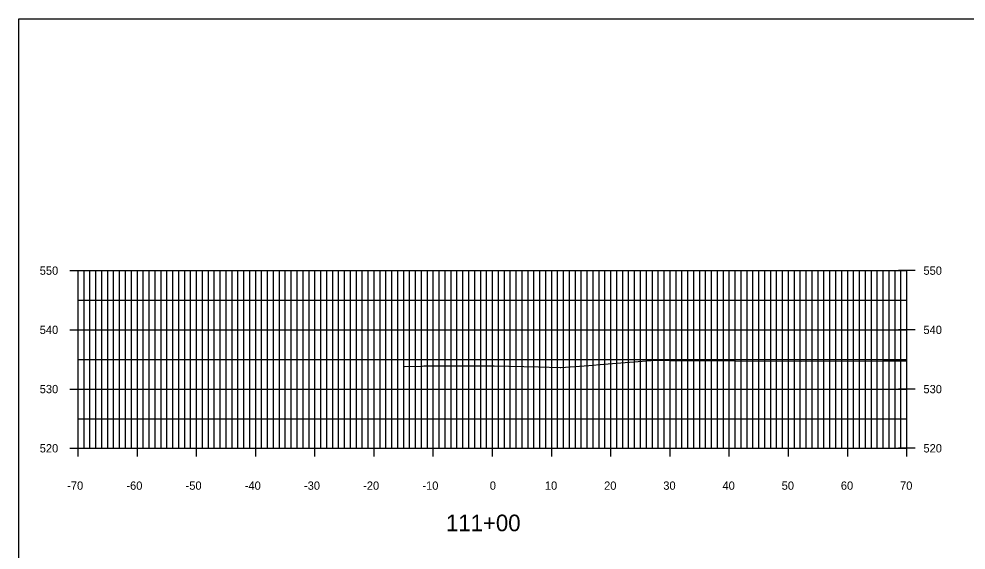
# Model space of a CAD drawing. Extents: x 1509063 to 1512863, y 401160 to 402918.
# Drawn here: x 1512542.7 to 1512702.7, y 402372.4 to 402462.1 of the extents above; entities that cross this region are included whole.
import ezdxf

# ---------------------------------------------------------------- set-up
doc = ezdxf.new("R2010")
doc.units = 0
for name, color, linetype in [('NBL1', 7, 'Continuous'), ('XAX_P', 7, 'Continuous'), ('XAXTIC_P', 7, 'Continuous'), ('XAXTXT_P_T', 7, 'Continuous'), ('XGL_P', 7, 'Continuous'), ('XSLOG', 7, 'Continuous')]:
    doc.layers.add(name, color=color, linetype=linetype)

msp = doc.modelspace()

# ---------------------------------------------------------------- linework, layer by layer
at = {"layer": 'NBL1'}
msp.add_lwpolyline([(1512862.73, 402252.08), (1512542.73, 402252.08), (1512542.73, 402462.08), (1512862.73, 402462.08)], close=True, dxfattribs=at)
at = {"layer": 'XAX_P'}
for p, q in [((1512552.73, 402389.58), (1512552.73, 402419.58)), ((1512622.73, 402389.58), (1512622.73, 402419.58)), ((1512692.73, 402389.58), (1512692.73, 402419.58)), ((1512552.73, 402389.58), (1512692.73, 402389.58))]:
    msp.add_line(p, q, dxfattribs=at)
at = {"layer": 'XAXTIC_P'}
for p, q in [((1512551.33, 402419.58), (1512554.13, 402419.58)), ((1512621.33, 402419.58), (1512624.13, 402419.58)), ((1512694.13, 402419.58), (1512691.33, 402419.58)), ((1512551.33, 402409.58), (1512554.13, 402409.58)), ((1512621.33, 402409.58), (1512624.13, 402409.58)), ((1512694.13, 402409.58), (1512691.33, 402409.58)), ((1512551.33, 402399.58), (1512554.13, 402399.58)), ((1512621.33, 402399.58), (1512624.13, 402399.58)), ((1512694.13, 402399.58), (1512691.33, 402399.58)), ((1512552.73, 402388.18), (1512552.73, 402390.98)), ((1512562.73, 402388.18), (1512562.73, 402390.98)), ((1512572.73, 402388.18), (1512572.73, 402390.98)), ((1512582.73, 402388.18), (1512582.73, 402390.98)), ((1512592.73, 402388.18), (1512592.73, 402390.98)), ((1512602.73, 402388.18), (1512602.73, 402390.98)), ((1512612.73, 402388.18), (1512612.73, 402390.98)), ((1512622.73, 402388.18), (1512622.73, 402390.98)), ((1512632.73, 402388.18), (1512632.73, 402390.98)), ((1512642.73, 402388.18), (1512642.73, 402390.98)), ((1512652.73, 402388.18), (1512652.73, 402390.98)), ((1512662.73, 402388.18), (1512662.73, 402390.98)), ((1512672.73, 402388.18), (1512672.73, 402390.98)), ((1512682.73, 402388.18), (1512682.73, 402390.98)), ((1512692.73, 402388.18), (1512692.73, 402390.98)), ((1512551.33, 402389.58), (1512554.13, 402389.58)), ((1512621.33, 402389.58), (1512624.13, 402389.58)), ((1512694.13, 402389.58), (1512691.33, 402389.58))]:
    msp.add_line(p, q, dxfattribs=at)
at = {"layer": 'XGL_P'}
for p, q in [((1512552.73, 402419.58), (1512692.73, 402419.58)), ((1512552.73, 402389.58), (1512552.73, 402419.58)), ((1512553.73, 402389.58), (1512553.73, 402419.58)), ((1512554.73, 402389.58), (1512554.73, 402419.58)), ((1512555.73, 402389.58), (1512555.73, 402419.58)), ((1512556.73, 402389.58), (1512556.73, 402419.58)), ((1512557.73, 402389.58), (1512557.73, 402419.58)), ((1512558.73, 402389.58), (1512558.73, 402419.58)), ((1512559.73, 402389.58), (1512559.73, 402419.58)), ((1512560.73, 402389.58), (1512560.73, 402419.58)), ((1512561.73, 402389.58), (1512561.73, 402419.58)), ((1512562.73, 402389.58), (1512562.73, 402419.58)), ((1512563.73, 402389.58), (1512563.73, 402419.58)), ((1512564.73, 402389.58), (1512564.73, 402419.58)), ((1512565.73, 402389.58), (1512565.73, 402419.58)), ((1512566.73, 402389.58), (1512566.73, 402419.58)), ((1512567.73, 402389.58), (1512567.73, 402419.58)), ((1512568.73, 402389.58), (1512568.73, 402419.58)), ((1512569.73, 402389.58), (1512569.73, 402419.58)), ((1512570.73, 402389.58), (1512570.73, 402419.58)), ((1512571.73, 402389.58), (1512571.73, 402419.58)), ((1512572.73, 402389.58), (1512572.73, 402419.58)), ((1512573.73, 402389.58), (1512573.73, 402419.58)), ((1512574.73, 402389.58), (1512574.73, 402419.58)), ((1512575.73, 402389.58), (1512575.73, 402419.58)), ((1512576.73, 402389.58), (1512576.73, 402419.58)), ((1512577.73, 402389.58), (1512577.73, 402419.58)), ((1512578.73, 402389.58), (1512578.73, 402419.58)), ((1512579.73, 402389.58), (1512579.73, 402419.58)), ((1512580.73, 402389.58), (1512580.73, 402419.58)), ((1512581.73, 402389.58), (1512581.73, 402419.58)), ((1512582.73, 402389.58), (1512582.73, 402419.58)), ((1512583.73, 402389.58), (1512583.73, 402419.58)), ((1512584.73, 402389.58), (1512584.73, 402419.58)), ((1512585.73, 402389.58), (1512585.73, 402419.58)), ((1512586.73, 402389.58), (1512586.73, 402419.58)), ((1512587.73, 402389.58), (1512587.73, 402419.58)), ((1512588.73, 402389.58), (1512588.73, 402419.58)), ((1512589.73, 402389.58), (1512589.73, 402419.58)), ((1512590.73, 402389.58), (1512590.73, 402419.58)), ((1512591.73, 402389.58), (1512591.73, 402419.58)), ((1512592.73, 402389.58), (1512592.73, 402419.58)), ((1512593.73, 402389.58), (1512593.73, 402419.58)), ((1512594.73, 402389.58), (1512594.73, 402419.58)), ((1512595.73, 402389.58), (1512595.73, 402419.58)), ((1512596.73, 402389.58), (1512596.73, 402419.58)), ((1512597.73, 402389.58), (1512597.73, 402419.58)), ((1512598.73, 402389.58), (1512598.73, 402419.58)), ((1512599.73, 402389.58), (1512599.73, 402419.58)), ((1512600.73, 402389.58), (1512600.73, 402419.58)), ((1512601.73, 402389.58), (1512601.73, 402419.58)), ((1512602.73, 402389.58), (1512602.73, 402419.58)), ((1512603.73, 402389.58), (1512603.73, 402419.58)), ((1512604.73, 402389.58), (1512604.73, 402419.58)), ((1512605.73, 402389.58), (1512605.73, 402419.58)), ((1512606.73, 402389.58), (1512606.73, 402419.58)), ((1512607.73, 402389.58), (1512607.73, 402419.58)), ((1512608.73, 402389.58), (1512608.73, 402419.58)), ((1512609.73, 402389.58), (1512609.73, 402419.58)), ((1512610.73, 402389.58), (1512610.73, 402419.58)), ((1512611.73, 402389.58), (1512611.73, 402419.58)), ((1512612.73, 402389.58), (1512612.73, 402419.58)), ((1512613.73, 402389.58), (1512613.73, 402419.58)), ((1512614.73, 402389.58), (1512614.73, 402419.58)), ((1512615.73, 402389.58), (1512615.73, 402419.58)), ((1512616.73, 402389.58), (1512616.73, 402419.58)), ((1512617.73, 402389.58), (1512617.73, 402419.58)), ((1512618.73, 402389.58), (1512618.73, 402419.58)), ((1512619.73, 402389.58), (1512619.73, 402419.58)), ((1512620.73, 402389.58), (1512620.73, 402419.58)), ((1512621.73, 402389.58), (1512621.73, 402419.58)), ((1512622.73, 402389.58), (1512622.73, 402419.58)), ((1512623.73, 402389.58), (1512623.73, 402419.58)), ((1512624.73, 402389.58), (1512624.73, 402419.58)), ((1512625.73, 402389.58), (1512625.73, 402419.58)), ((1512626.73, 402389.58), (1512626.73, 402419.58)), ((1512627.73, 402389.58), (1512627.73, 402419.58)), ((1512628.73, 402389.58), (1512628.73, 402419.58)), ((1512629.73, 402389.58), (1512629.73, 402419.58)), ((1512630.73, 402389.58), (1512630.73, 402419.58)), ((1512631.73, 402389.58), (1512631.73, 402419.58)), ((1512632.73, 402389.58), (1512632.73, 402419.58)), ((1512633.73, 402389.58), (1512633.73, 402419.58)), ((1512634.73, 402389.58), (1512634.73, 402419.58)), ((1512635.73, 402389.58), (1512635.73, 402419.58)), ((1512636.73, 402389.58), (1512636.73, 402419.58)), ((1512637.73, 402389.58), (1512637.73, 402419.58)), ((1512638.73, 402389.58), (1512638.73, 402419.58)), ((1512639.73, 402389.58), (1512639.73, 402419.58)), ((1512640.73, 402389.58), (1512640.73, 402419.58)), ((1512641.73, 402389.58), (1512641.73, 402419.58)), ((1512642.73, 402389.58), (1512642.73, 402419.58)), ((1512643.73, 402389.58), (1512643.73, 402419.58)), ((1512644.73, 402389.58), (1512644.73, 402419.58)), ((1512645.73, 402389.58), (1512645.73, 402419.58)), ((1512646.73, 402389.58), (1512646.73, 402419.58)), ((1512647.73, 402389.58), (1512647.73, 402419.58)), ((1512648.73, 402389.58), (1512648.73, 402419.58)), ((1512649.73, 402389.58), (1512649.73, 402419.58)), ((1512650.73, 402389.58), (1512650.73, 402419.58)), ((1512651.73, 402389.58), (1512651.73, 402419.58)), ((1512652.73, 402389.58), (1512652.73, 402419.58)), ((1512653.73, 402389.58), (1512653.73, 402419.58)), ((1512654.73, 402389.58), (1512654.73, 402419.58)), ((1512655.73, 402389.58), (1512655.73, 402419.58)), ((1512656.73, 402389.58), (1512656.73, 402419.58)), ((1512657.73, 402389.58), (1512657.73, 402419.58)), ((1512658.73, 402389.58), (1512658.73, 402419.58)), ((1512659.73, 402389.58), (1512659.73, 402419.58)), ((1512660.73, 402389.58), (1512660.73, 402419.58)), ((1512661.73, 402389.58), (1512661.73, 402419.58)), ((1512662.73, 402389.58), (1512662.73, 402419.58)), ((1512663.73, 402389.58), (1512663.73, 402419.58)), ((1512664.73, 402389.58), (1512664.73, 402419.58)), ((1512665.73, 402389.58), (1512665.73, 402419.58)), ((1512666.73, 402389.58), (1512666.73, 402419.58)), ((1512667.73, 402389.58), (1512667.73, 402419.58)), ((1512668.73, 402389.58), (1512668.73, 402419.58)), ((1512669.73, 402389.58), (1512669.73, 402419.58)), ((1512670.73, 402389.58), (1512670.73, 402419.58)), ((1512671.73, 402389.58), (1512671.73, 402419.58)), ((1512672.73, 402389.58), (1512672.73, 402419.58)), ((1512673.73, 402389.58), (1512673.73, 402419.58)), ((1512674.73, 402389.58), (1512674.73, 402419.58)), ((1512675.73, 402389.58), (1512675.73, 402419.58)), ((1512676.73, 402389.58), (1512676.73, 402419.58)), ((1512677.73, 402389.58), (1512677.73, 402419.58)), ((1512678.73, 402389.58), (1512678.73, 402419.58)), ((1512679.73, 402389.58), (1512679.73, 402419.58)), ((1512680.73, 402389.58), (1512680.73, 402419.58)), ((1512681.73, 402389.58), (1512681.73, 402419.58)), ((1512682.73, 402389.58), (1512682.73, 402419.58)), ((1512683.73, 402389.58), (1512683.73, 402419.58)), ((1512684.73, 402389.58), (1512684.73, 402419.58)), ((1512685.73, 402389.58), (1512685.73, 402419.58)), ((1512686.73, 402389.58), (1512686.73, 402419.58)), ((1512687.73, 402389.58), (1512687.73, 402419.58)), ((1512688.73, 402389.58), (1512688.73, 402419.58)), ((1512689.73, 402389.58), (1512689.73, 402419.58)), ((1512690.73, 402389.58), (1512690.73, 402419.58)), ((1512691.73, 402389.58), (1512691.73, 402419.58)), ((1512692.73, 402389.58), (1512692.73, 402419.58)), ((1512552.73, 402414.58), (1512692.73, 402414.58)), ((1512552.73, 402409.58), (1512692.73, 402409.58)), ((1512552.73, 402404.58), (1512692.73, 402404.58)), ((1512552.73, 402399.58), (1512692.73, 402399.58)), ((1512552.73, 402394.58), (1512692.73, 402394.58)), ((1512552.73, 402389.58), (1512692.73, 402389.58))]:
    msp.add_line(p, q, dxfattribs=at)
at = {"layer": 'XSLOG'}
msp.add_lwpolyline([(1512607.85, 402403.38), (1512610.83, 402403.47), (1512611.12, 402403.48), (1512622.4, 402403.53), (1512622.99, 402403.53), (1512630.51, 402403.33), (1512634.14, 402403.23), (1512634.3, 402403.24), (1512638.99, 402403.59), (1512641.53, 402403.78), (1512650.22, 402404.46), (1512652.71, 402404.43), (1512674.89, 402404.31), (1512688.6, 402404.34), (1512692.73, 402404.33)], dxfattribs=at)

# ---------------------------------------------------------------- texts
at = {"layer": 'XAXTXT_P_T'}
for s, height, p in [('550', 1.4, (1512546.24, 402418.88)), ('550', 1.4, (1512695.53, 402418.88)), ('540', 1.4, (1512546.24, 402408.88)), ('540', 1.4, (1512695.53, 402408.88)), ('530', 1.4, (1512546.24, 402398.88)), ('530', 1.4, (1512695.53, 402398.88)), ('520', 1.4, (1512546.24, 402388.88)), ('520', 1.4, (1512695.53, 402388.88)), ('-70', 1.4, (1512550.88, 402382.58)), ('-60', 1.4, (1512560.88, 402382.58)), ('-50', 1.4, (1512570.88, 402382.58)), ('-40', 1.4, (1512580.88, 402382.58)), ('-30', 1.4, (1512590.88, 402382.58)), ('-20', 1.4, (1512600.88, 402382.58)), ('-10', 1.4, (1512610.88, 402382.58)), ('0', 1.4, (1512622.27, 402382.58)), ('10', 1.4, (1512631.58, 402382.58)), ('20', 1.4, (1512641.58, 402382.58)), ('30', 1.4, (1512651.58, 402382.58)), ('40', 1.4, (1512661.58, 402382.58)), ('50', 1.4, (1512671.58, 402382.58)), ('60', 1.4, (1512681.58, 402382.58)), ('70', 1.4, (1512691.58, 402382.58)), ('111+00', 2.8, (1512614.87, 402375.58))]:
    msp.add_text(s, height=height, dxfattribs=at).set_placement(p)

doc.saveas('drawing.dxf')
